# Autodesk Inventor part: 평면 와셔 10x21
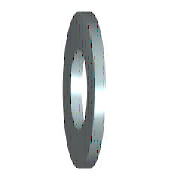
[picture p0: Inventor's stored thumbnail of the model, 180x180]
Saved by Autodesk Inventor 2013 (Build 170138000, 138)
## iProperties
IsCustomPart: 1
Created: 2012-02
Part Number: 평면 와셔 10x21
Material: 강철, 연강
Description: 평면 와셔
Document SubType Name: Modeling
Standard: KS B 1326
Designer: mduedu
Standards Organization: KS
Language: ko-KR
Size Designation: 10x21
Categories: <MemberInstance><Categories><Category DisplayName="조임쇠" InternalName="e4da775c-781d-43d5-af7c-5136215cf5a6" Mnemonic="FSTN"><Category DisplayName="와셔" InternalN
Density: 1 g/cm^3
Author: mduedu
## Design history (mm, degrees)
sketch "스케치"
  geometry: C1 r 10.5 at (0, 0); C2 r 5.25 at (0, 0); 1 further point
  constraints: 2 centre point, 2 coincident
  dimensions: "d0" = 10.5 diameter of C2 (= SD1); "d1" = 21 diameter of C1 (= SD2)
extrude "본체" new body sketch "스케치" distance "d2" = 2 (= SD); taper "d3" = 0 deg
workaxis "Work Axis1"
workplane "Work Plane1"
body "Solid1"
other parameters: "SD1" = 10.5 [user parameter; used in 1 equation term], "SD2" = 21 [user parameter; used in 1 equation term], "SD" = 2 [user parameter; used in 1 equation term], "d4" = 0, "d5" = 0, "d6" = 0, "d7" = 0
